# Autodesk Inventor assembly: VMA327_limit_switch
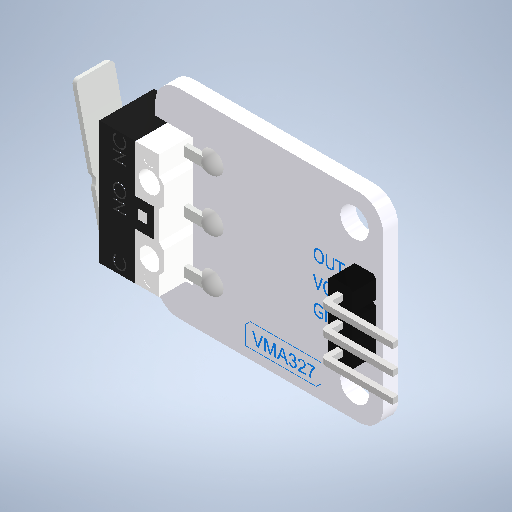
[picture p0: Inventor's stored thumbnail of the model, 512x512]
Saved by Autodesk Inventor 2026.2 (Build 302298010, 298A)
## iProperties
Created: 2023-02
Part Number: VMA327_limit_switch
Document SubType Name: Assembly
Designer: mel
Sending System: Autodesk Inventor 2020
Preprocessor: ST-DEVELOPER v18
Title: D:\Documenten\Inventor\Project files\Strijkkralen sorteermachine\VMA327_limit_switch.stp
Author: Gebruiker
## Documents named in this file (6)
- D:\travail\année 2026-2027\1 sti2d IT\poubelle à verre\vma327-limit-switch-1.snapshot.2\VMA327_limit_switch\VMA327_limit_switch\VMA327_limit_switch.iam
- D:\travail\année 2026-2027\1 sti2d IT\poubelle à verre\vma327-limit-switch-1.snapshot.2\VMA327_limit_switch\VMA327_limit_switch\VMA327_PCB.ipt
- D:\travail\année 2026-2027\1 sti2d IT\poubelle à verre\vma327-limit-switch-1.snapshot.2\VMA327_limit_switch\VMA327_limit_switch\Limit_Switch.ipt
- D:\travail\année 2026-2027\1 sti2d IT\poubelle à verre\vma327-limit-switch-1.snapshot.2\VMA327_limit_switch\VMA327_limit_switch\Haakse_PCB_connector.ipt
- D:\travail\année 2026-2027\1 sti2d IT\poubelle à verre\vma327-limit-switch-1.snapshot.2\VMA327_limit_switch\VMA327_limit_switch\Soldeerpunt.ipt
- D:\travail\année 2026-2027\1 sti2d IT\poubelle à verre\vma327-limit-switch-1.snapshot.2\VMA327_limit_switch\VMA327_limit_switch\Soldeerdruppel.ipt
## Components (9 placed, 5 different names)
1. VMA327_PCB:1
2. Limit_Switch:1
3. Haakse_PCB_connector:1
4. Soldeerpunt:1
5. Soldeerpunt:2
6. Soldeerpunt:3
7. Soldeerdruppel:1
8. Soldeerdruppel:2
9. Soldeerdruppel:3
